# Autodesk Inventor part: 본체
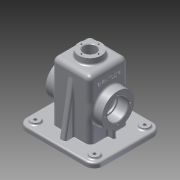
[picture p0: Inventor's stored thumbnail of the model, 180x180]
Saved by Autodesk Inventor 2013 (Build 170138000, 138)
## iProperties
Created: 2016-01
Part Number: 본체
Material: 알루미늄 6061
Document SubType Name: Modeling
Designer: Administrator
Density: 2.71 g/cm^3
Mass: 806.61 g
Surface Area: 908.304 cm^2
Volume: 297.642 cm^3
Author: Administrator
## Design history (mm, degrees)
sketch "스케치1"
  geometry: L1 (-65, -57.5)-(65, -57.5); L2 (65, -57.5)-(65, 57.5); L3 (65, 57.5)-(-65, 57.5); L4 (-65, 57.5)-(-65, -57.5); 3 further points
  constraints: 8 end point, 2 midpoint, 2 parallel, 1 horizontal, 1 horizontal alignment, 1 perpendicular, 1 vertical alignment
  dimensions: "d0" = 130 distance of L2.end L3.end; "d2" = 115 distance of L1.end L2.end
extrude "돌출1" new body sketch "스케치1" distance "d3" = 8; taper "d4" = 0 deg
fillet "모깎기1" dims "d5" = 15
sketch "스케치2"
  geometry: L1 (-65, -42.5)-(-65, 42.5) reference; L2 (50, -57.5)-(-50, -57.5) reference; L3 (65, 42.5)-(65, -42.5) reference; L4 (-50, 57.5)-(50, 57.5) reference; L5 (-65, -42.5)-(-65, 42.5) reference; L6 (50, -57.5)-(-50, -57.5) reference; L7 (65, 42.5)-(65, -42.5) reference; L8 (-50, 57.5)-(50, 57.5) reference; L9 (-60, -42.5)-(-60, 42.5); L10 (-50, 52.5)-(50, 52.5); L11 (60, 42.5)-(60, -42.5); L12 (50, -52.5)-(-50, -52.5); A1 r 15 centre (-50, 42.5) between (-50, 57.5) and (-65, 42.5) reference; A2 r 15 centre (-50, -42.5) between (-65, -42.5) and (-50, -57.5) reference; A3 r 15 centre (50, -42.5) between (50, -57.5) and (65, -42.5) reference; A4 r 15 centre (50, 42.5) between (65, 42.5) and (50, 57.5) reference; A5 r 15 centre (-50, 42.5) between (-50, 57.5) and (-65, 42.5) reference; A6 r 15 centre (-50, -42.5) between (-65, -42.5) and (-50, -57.5) reference; A7 r 15 centre (50, -42.5) between (50, -57.5) and (65, -42.5) reference; A8 r 15 centre (50, 42.5) between (65, 42.5) and (50, 57.5) reference; A9 r 10 centre (-50, -42.5) between (-60, -42.5) and (-50, -52.5); A10 r 10 centre (-50, 42.5) between (-50, 52.5) and (-60, 42.5); A11 r 10 centre (50, 42.5) between (60, 42.5) and (50, 52.5); A12 r 10 centre (50, -42.5) between (50, -52.5) and (60, -42.5); 1 further point
  constraints: 8 end point, 8 point on circle, 4 centre point, 7 other
  dimensions: "d6" = 5 distance between parallel lines of L2 L12
extrude "돌출2" join sketch "스케치2" distance "d7" = 2; taper "d8" = 0 deg
sketch "스케치3"
  geometry: A1 r 10 centre (-50, -42.5) between (-60, -42.5) and (-50, -52.5) reference; A2 r 10 centre (50, -42.5) between (50, -52.5) and (60, -42.5) reference; A3 r 10 centre (50, 42.5) between (60, 42.5) and (50, 52.5) reference; A4 r 10 centre (-50, 42.5) between (-50, 52.5) and (-60, 42.5) reference; 1 further point
hole "구멍1" sketch "스케치3" at (50, -42.5), (-50, -42.5), (-50, 42.5), (50, 42.5) diameter "d9" = 5; stored, may be unused: countersink angle "d13" = 90 deg, drill point angle "d15" = 0 deg; dims "d10" = 6, "d11" = 4, "d12" = 2, "d14" = 13
sketch "스케치4"
  geometry: C1 r 2.5 at (50, 42.5) reference; C2 r 2.5 at (-50, -42.5) reference; C3 r 2.5 at (50, -42.5) reference; C4 r 2.5 at (-50, 42.5) reference; C5 r 7.5 at (-50, 42.5); C6 r 7.5 at (50, 42.5); C7 r 7.5 at (50, -42.5); C8 r 7.5 at (-50, -42.5); A1 r 15 centre (50, 42.5) between (65, 42.5) and (50, 57.5) reference; A2 r 15 centre (-50, 42.5) between (-50, 57.5) and (-65, 42.5) reference; A3 r 15 centre (-50, -42.5) between (-65, -42.5) and (-50, -57.5) reference; A4 r 15 centre (50, -42.5) between (50, -57.5) and (65, -42.5) reference; 1 further point
  constraints: 4 centre point, 4 coincident
  dimensions: "d16" = 15 diameter of C5; "d17" = 15 diameter of C6; "d18" = 15 diameter of C7; "d19" = 15 diameter of C8
extrude "돌출3" join sketch "스케치4" distance "d20" = 3; taper "d21" = 0 deg
fillet "모깎기2" dims "d22" = 3
fillet "모깎기3" dims "d23" = 3
sketch "스케치5"
  geometry: L1 (-32.5, 32.5)-(32.5, 32.5); L2 (32.5, 32.5)-(32.5, -32.5); L3 (32.5, -32.5)-(-32.5, -32.5); L4 (-32.5, -32.5)-(-32.5, 32.5); 3 further points
  constraints: 8 end point, 2 midpoint, 2 parallel, 1 horizontal, 1 horizontal alignment, 1 perpendicular, 1 vertical alignment
  dimensions: "d24" = 65 distance of L1.start L1.end; "d26" = 65 distance of L3.end L1.start
extrude "돌출4" join sketch "스케치5" distance "d27" = 100; taper "d28" = 0 deg
sketch "스케치6"
  geometry: L1 (27.5, -27.5)-(-27.5, -27.5); L2 (-27.5, -27.5)-(-27.5, 27.5); L3 (-27.5, 27.5)-(27.5, 27.5); L4 (27.5, 27.5)-(27.5, -27.5); 3 further points
  constraints: 8 end point, 2 midpoint, 2 parallel, 1 horizontal, 1 horizontal alignment, 1 perpendicular, 1 vertical alignment
  dimensions: "d31" = 55 distance of L1.start L1.end; "d33" = 55 distance of L3.end L1.start
extrude "돌출5" cut sketch "스케치6" distance "d34" = 105; taper "d35" = 0 deg
sketch "스케치7"
  geometry: C1 r 20 at (0, 0); 1 further point
  constraints: 1 centre point, 1 coincident
  dimensions: "d36" = 40 diameter of C1
extrude "돌출6" join sketch "스케치7" distance "d37" = 10; taper "d38" = 0 deg
feature "면 기울기1" dims angle "d39" = 5 deg
fillet "모깎기6" dims "d40" = 3
sketch "스케치8"
  geometry: C1 r 19.125 at (0, 0) reference; C2 r 10.5 at (0, 0)
  constraints: 1 centre point, 1 coincident
  dimensions: "d41" = 21 diameter of C2
extrude "돌출7" cut sketch "스케치8" distance "d42" = 15; taper "d43" = 0 deg
chamfer "모따기1" distance "d44" = 1; stored, may be unused: second distance "d45" = 2, angle "d46" = 45 deg
sketch "스케치9" dims "d47" = 29
  geometry: L1 (0, 0)-(0, 14.5); C1 r 11.5 at (0, 0) reference; 1 further point
  constraints: 2 coincident, 2 end point, 1 vertical, 1 vertical alignment, 2 other
hole "구멍2" sketch "스케치9" at (0, 14.5) diameter "d48" = 2.459; stored, may be unused: countersink angle "d52" = 90 deg, drill point angle "d54" = 118 deg; dims "d49" = 7, "d50" = 4, "d51" = 2, "d53" = 9
sketch "스케치10"
  geometry: L1 (10, -28)-(8, -28) reference; L2 (8, -28)-(8, -33) reference; L3 (8, -33)-(3, -33) reference; L4 (0, -30)-(0, -8) reference; L5 (0, 57)-(0, 79) reference; L6 (3, 82)-(8, 82) reference; L7 (8, 82)-(8, 77) reference; L8 (8, 77)-(10, 77) reference; L9 (10, 77)-(10, -28) reference; L10 (10, -28)-(8, -28) reference; L11 (8, -28)-(8, -33) reference; L12 (8, -33)-(3, -33) reference; L13 (0, -30)-(0, -8) reference; L14 (0, 57)-(0, 79) reference; L15 (3, 82)-(8, 82) reference; L16 (8, 82)-(8, 77) reference; L17 (8, 77)-(10, 77) reference; L18 (10, 77)-(10, -28) reference; L19 (0, -8)-(-100, -8) reference; L20 (-100, 57)-(0, 57) reference; L21 (0, -8)-(0, 57) reference; L22 (0, -8)-(-100, -8) reference; L23 (-100, 57)-(0, 57) reference; L24 (0, -8)-(0, 57) reference; L25 (-100, -8)-(-100, 57) reference; L26 (-100, -8)-(-100, 57) reference; C1 r 27.5 at (-45, 24.5); A1 r 3 centre (3, -30) between (0, -30) and (3, -33) reference; A2 r 3 centre (3, 79) between (3, 82) and (0, 79) reference; A3 r 3 centre (3, -30) between (0, -30) and (3, -33) reference; A4 r 3 centre (3, 79) between (3, 82) and (0, 79) reference; 2 further points
  constraints: 1 centre point, 1 horizontal alignment, 1 midpoint
  dimensions: "d58" = 55 diameter of C1; "d59" = 55 distance of point (10, 24.5) C1.centre
extrude "돌출8" join sketch "스케치10" distance "d60" = 15; taper "d61" = 0 deg
sketch "스케치11"
  geometry: C1 r 27.5 at (0, 0) reference; C2 r 17.5 at (0, 0); 1 further point
  constraints: 1 centre point, 1 coincident
  dimensions: "d62" = 35 diameter of C2
extrude "돌출9" cut sketch "스케치11" distance "d63" = 17; taper "d64" = 0 deg
sketch "스케치12" dims "d65" = 42
  geometry: L1 (0, 0)-(-21, 0); C1 r 27.5 at (0, 0) reference; 2 further points
  constraints: 2 coincident, 2 end point, 1 horizontal, 1 horizontal alignment, 2 other
hole "구멍3" sketch "스케치12" at (-21, 0) diameter "d66" = 3.242; stored, may be unused: countersink angle "d70" = 90 deg, drill point angle "d72" = 118 deg; dims "d67" = 8, "d68" = 4, "d69" = 2, "d71" = 10
sketch "스케치13"
  geometry: C1 r 17.5 at (0, 0) reference; C2 r 15 at (0, 0); 1 further point
  constraints: 1 centre point, 1 coincident
  dimensions: "d76" = 30 diameter of C2
extrude "돌출10" cut sketch "스케치13" distance "d77" = 3; taper "d78" = 0 deg
chamfer "모따기2" distance "d79" = 1; stored, may be unused: second distance "d80" = 2, angle "d81" = 45 deg
fillet "모깎기7" dims "d82" = 0.3
fillet "모깎기8" dims "d83" = 3
fillet "모깎기9" dims "d84" = 3
node "작업 평면1"
node "작업 평면2"
sketch "스케치15"
  geometry: L1 (100, 77)-(102, 77) reference; L2 (102, 77)-(102, 52) reference; L3 (102, 52)-(0, 52) reference; L4 (-3, 49)-(-3, 35) reference; L5 (-3, 35)-(-17, 35) reference; L6 (-17, 35)-(-18, 36) reference; L7 (-18, 36)-(-18, 37.77) reference; L8 (-18, 37.77)-(-9, 37.77) reference; L9 (-9, 37.77)-(-8.261, 39) reference; L10 (-8.261, 39)-(-9, 40.23) reference; L11 (-9, 40.23)-(-18, 40.23) reference; L12 (-18, 40.23)-(-18, 43.625) reference; L13 (-18, 43.625)-(-10.739, 44.26) reference; L14 (-8, 47.249)-(-8, 57) reference; L15 (-8, 57)-(92, 57) reference; L16 (92, 57)-(92, 79) reference; L17 (95, 82)-(100, 82) reference; L18 (100, 82)-(100, 77) reference; L19 (102, -28)-(100, -28) reference; L20 (100, -28)-(100, -33) reference; L21 (100, -33)-(95, -33) reference; L22 (92, -30)-(92, -8) reference; L23 (92, -8)-(-8, -8) reference; L24 (-8, -8)-(-8, 1.751) reference; L25 (-10.739, 4.74)-(-18, 5.375) reference; L26 (-18, 5.375)-(-18, 8.77) reference; L27 (-18, 8.77)-(-9, 8.77) reference; L28 (-9, 8.77)-(-8.261, 10) reference; L29 (-8.261, 10)-(-9, 11.229) reference; L30 (-9, 11.229)-(-18, 11.229) reference; L31 (-18, 11.229)-(-18, 13) reference; L32 (-18, 13)-(-17, 14) reference; L33 (-17, 14)-(-3, 14) reference; L34 (-3, 14)-(-3, 0) reference; L35 (0, -3)-(102, -3) reference; L36 (102, -3)-(102, -28) reference; L37 (92, -23)-(6.931, -8); L38 (92, 72)-(6.931, 57); L39 (6.931, -8)-(92, -8); L40 (92, -8)-(92, -23); L41 (6.931, 57)-(92, 57); L42 (92, 57)-(92, 72); A1 r 3 centre (0, 49) between (0, 52) and (-3, 49) reference; A2 r 3 centre (-11, 47.249) between (-10.739, 44.26) and (-8, 47.249) reference; A3 r 3 centre (95, 79) between (95, 82) and (92, 79) reference; A4 r 3 centre (95, -30) between (92, -30) and (95, -33) reference; A5 r 3 centre (-11, 1.751) between (-8, 1.751) and (-10.739, 4.74) reference; A6 r 3 centre (0, 0) between (-3, 0) and (0, -3) reference; 1 further point
  constraints: 12 end point, 4 point on line, 2 horizontal, 2 vertical
  dimensions: "d89" = 10 distance from line of L21 L37.start; "d90" = 100 deg angle of L22 L37; "d91" = 10 distance from line of L17 L38.start; "d92" = 100 deg angle of L16 L38
extrude "돌출12" join sketch "스케치15" stored distance "d93" = 10; taper "d94" = 0 deg
fillet "모깎기10" dims "d95" = 3
fillet "모깎기11" dims "d96" = 3
fillet "모깎기12" dims "d97" = 3
fillet "모깎기13" dims "d98" = 3
fillet "모깎기14" dims "d99" = 3
fillet "모깎기15" dims "d100" = 3
node "작업 평면3"
node "작업 평면4"
node "작업 평면5"
sketch "스케치17"
  geometry: L1 (12.74, 2.739)-(13.375, 10) reference; L2 (13.375, 10)-(16.77, 10) reference; L3 (16.77, 10)-(16.77, 1) reference; L4 (16.77, 1)-(18, 0.261) reference; L5 (18, 0.261)-(19.229, 1) reference; L6 (19.229, 1)-(19.229, 10) reference; L7 (19.229, 10)-(21, 10) reference; L8 (21, 10)-(22, 9) reference; L9 (22, 9)-(22, -5) reference; L10 (22, -5)-(8, -5) reference; L11 (5, -8)-(5, -40) reference; L12 (5, -40)-(2, -40) reference; L13 (2, -40)-(2, -37.8) reference; L14 (1.7, -37.5)-(-14, -37.5) reference; L15 (-14, -37.5)-(-15, -36.5) reference; L16 (-15, -36.5)-(-15, -35.621) reference; L17 (-15, -35.621)-(-5, -35.621) reference; L18 (-5, -35.621)-(-4.026, -34) reference; L19 (-4.026, -34)-(-5, -32.379) reference; L20 (-5, -32.379)-(-15, -32.379) reference; L21 (-15, -32.379)-(-15, -27.5) reference; L22 (-15, -27.5)-(0, -27.5) reference; L23 (0, -27.5)-(0, 0) reference; L24 (0, 0)-(9.751, 0) reference; L25 (55.249, 0)-(65, 0) reference; L26 (65, 0)-(65, -27.5) reference; L27 (65, -27.5)-(80, -27.5) reference; L28 (80, -27.5)-(80, -32.379) reference; L29 (80, -32.379)-(70, -32.379) reference; L30 (70, -32.379)-(69.026, -34) reference; L31 (69.026, -34)-(70, -35.621) reference; L32 (70, -35.621)-(80, -35.621) reference; L33 (80, -35.621)-(80, -36.5) reference; L34 (80, -36.5)-(79, -37.5) reference; L35 (79, -37.5)-(63.3, -37.5) reference; L36 (63, -37.8)-(63, -40) reference; L37 (63, -40)-(60, -40) reference; L38 (60, -40)-(60, -8) reference; L39 (57, -5)-(43, -5) reference; L40 (43, -5)-(43, 9) reference; L41 (43, 9)-(44, 10) reference; L42 (44, 10)-(45.77, 10) reference; L43 (45.77, 10)-(45.77, 1) reference; L44 (45.77, 1)-(47, 0.261) reference; L45 (47, 0.261)-(48.229, 1) reference; L46 (48.229, 1)-(48.229, 10) reference; L47 (48.229, 10)-(51.625, 10) reference; L48 (51.625, 10)-(52.26, 2.739) reference; L49 (92.5, -108)-(92.5, -110) reference; L50 (92.5, -110)-(60, -110) reference; L51 (60, -110)-(60, -70) reference; L52 (60, -70)-(63, -70) reference; L53 (63, -70)-(63, -72.2) reference; L54 (63.3, -72.5)-(79, -72.5) reference; L55 (79, -72.5)-(80, -73.5) reference; L56 (80, -73.5)-(80, -74.379) reference; L57 (80, -74.379)-(70, -74.379) reference; L58 (70, -74.379)-(69.026, -76) reference; L59 (69.026, -76)-(70, -77.621) reference; L60 (70, -77.621)-(80, -77.621) reference; L61 (80, -77.621)-(80, -82.5) reference; L62 (80, -82.5)-(65, -82.5) reference; L63 (65, -82.5)-(65, -100) reference; L64 (65, -100)-(94.5, -100) reference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; A1 r 3 centre (9.751, 3) between (9.751, 0) and (12.74, 2.739) reference; A2 r 3 centre (8, -8) between (8, -5) and (5, -8) reference; A3 r 0.3 centre (1.7, -37.8) between (2, -37.8) and (1.7, -37.5) reference; A4 r 3 centre (55.249, 3) between (52.26, 2.739) and (55.249, 0) reference; A5 r 0.3 centre (63.3, -37.8) between (63.3, -37.5) and (63, -37.8) reference; A6 r 3 centre (57, -8) between (60, -8) and (57, -5) reference; A7 r 0.3 centre (63.3, -72.2) between (63, -72.2) and (63.3, -72.5) reference; A8 r 3 centre (94.5, -103) between (97.5, -103) and (94.5, -100) reference; A9 r 3 centre (-29.5, -103) between (-29.5, -100) and (-32.5, -103) reference; A10 r 0.3 centre (1.7, -72.2) between (1.7, -72.5) and (2, -72.2) reference; 1 further point
  constraints: 14 end point, 4 horizontal, 3 point on line, 3 vertical
  dimensions: "d112" = 15 distance between parallel lines of L51 L86; "d113" = 20 distance between parallel lines of L89 L87; "d114" = 15 distance between parallel lines of L83 L90; "d115" = 20 distance between parallel lines of L85 L91
extrude "돌출14" join sketch "스케치17" stored distance "d116" = 6; taper "d117" = 0 deg
fillet "모깎기21" dims "d118" = 3
fillet "모깎기22" dims "d119" = 3
fillet "모깎기23" dims "d120" = 3
fillet "모깎기24" dims "d121" = 3
fillet "모깎기25" dims "d122" = 8
fillet "모깎기26" dims "d123" = 8
fillet "모깎기27" dims "d124" = 1
sketch "스케치18"
  geometry: L1 (-65, 19.125)-(-65, -19.125) reference; 3 further points
  constraints: 1 horizontal alignment, 1 midpoint, 1 other
  dimensions: "d125" = 27 distance from line of point (-38, 0) L1
feature "엠보싱1" sketch "스케치18" dims "d126" = 0.5, "d127" = 0
node "솔리드1"
pattern_circular "원형 패턴1" dims angle "d56" = 360 deg
pattern_circular "원형 패턴2" dims angle "d74" = 360 deg
mirror "대칭1"
node "투영된 루프1"
node "절단 모서리 투영1"
node "절단 모서리 투영2"
node "절단 모서리 투영4"
node "절단 모서리 투영6"
other parameters: "d106" = 32.5
